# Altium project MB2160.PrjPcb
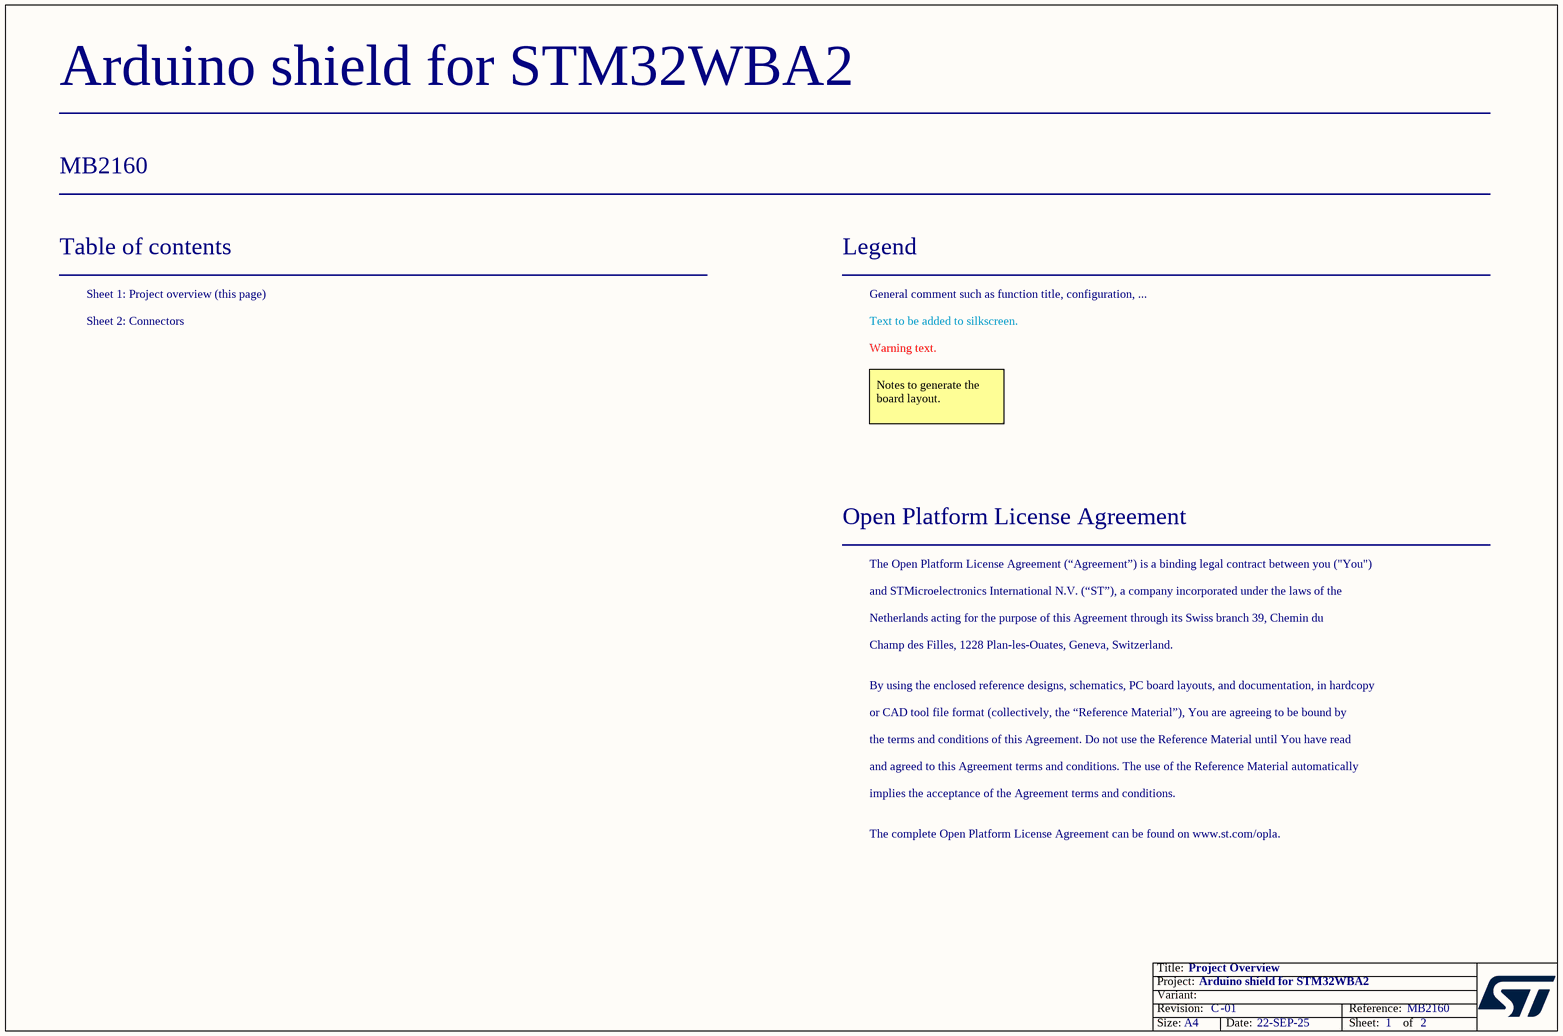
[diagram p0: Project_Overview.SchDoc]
Board_Reference: MB2160; Board_PCB_Revision: C; Board_Name: Arduino shield for STM32WBA2; Board_Document_Date: 22-SEP-25; Board_Assembly_Revision: 01
2 sheets, 28 parts. Net scope: global (net labels, ports and power ports of the same name join across sheets).
Board file: MB2160.PcbDoc
Sheets:
  Project_Overview.SchDoc
  Connectors.SchDoc

## Sheet Project_Overview.SchDoc: Project Overview
size A4; Date: Not used; ApprovedBy: Not used; CheckedBy: Not used; Author: Not used; CompanyName: STMicroelectronics; DrawnBy: Not used; Engineer: Not used; Organization: Not used; Address1: Not used; Address2: Not used; Address3: Not used; Address4: Not used; DocumentNumber: 1; Revision: Not used; SheetNumber: 1; SheetTotal: 2

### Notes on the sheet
- Table of contents
- Sheet 1: Project overview (this page)
- Legend
- General comment such as function title, configuration, ...
- Sheet 2: Connectors
- Text to be added to silkscreen.
- Warning text.
- Notes to generate the board layout.
- Open Platform License Agreement
- The Open Platform License Agreement (“Agreement”) is a binding legal contract between you ("You")
- and STMicroelectronics International N.V. (“ST”), a company incorporated under the laws of the
- Netherlands acting for the purpose of this Agreement through its Swiss branch 39, Chemin du
- Champ des Filles, 1228 Plan-les-Ouates, Geneva, Switzerland.
- By using the enclosed reference designs, schematics, PC board layouts, and documentation, in hardcopy
- or CAD tool file format (collectively, the “Reference Material”), You are agreeing to be bound by
- the terms and conditions of this Agreement. Do not use the Reference Material until You have read
- and agreed to this Agreement terms and conditions. The use of the Reference Material automatically
- implies the acceptance of the Agreement terms and conditions.
- The complete Open Platform License Agreement can be found on www.st.com/opla.

## Sheet Connectors.SchDoc: Arduino
size A4; Date: Not used; ApprovedBy: Not used; CheckedBy: Not used; Author: Not used; CompanyName: STMicroelectronics; DrawnBy: Not used; Engineer: Not used; Organization: Not used; Address1: Not used; Address2: Not used; Address3: Not used; Address4: Not used; DocumentNumber: 2; Revision: Not used; SheetNumber: 2; SheetTotal: 2
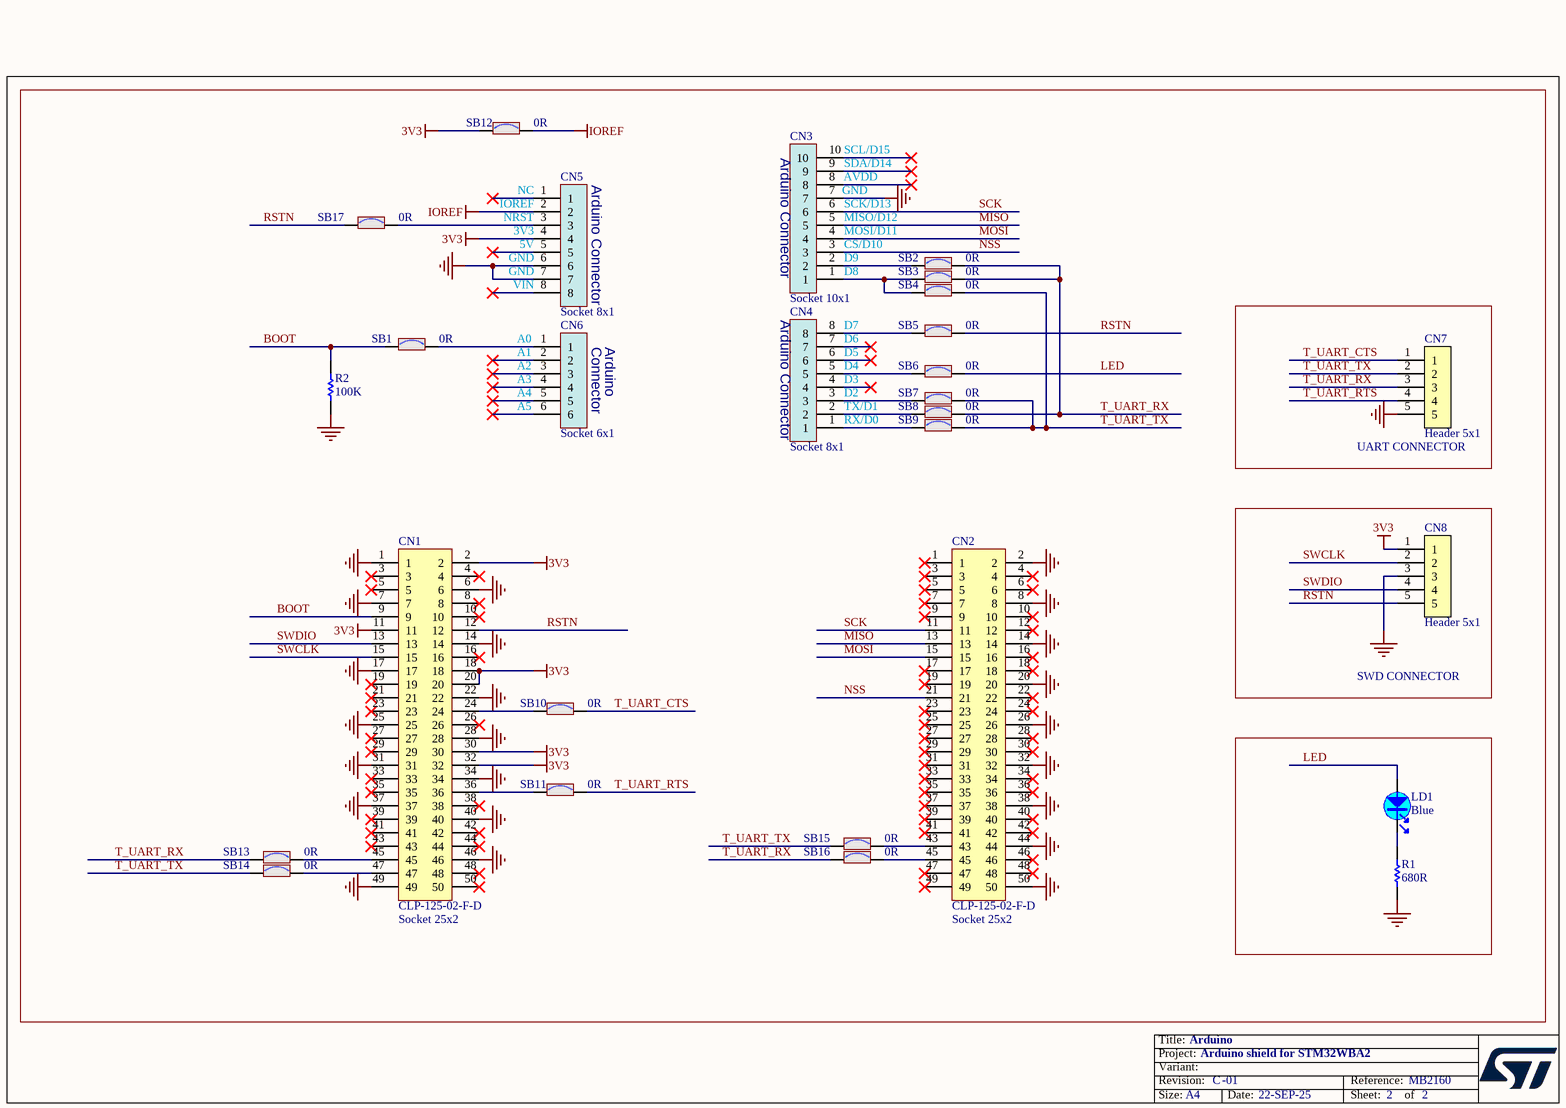
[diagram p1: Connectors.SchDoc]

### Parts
CN1  CLP-125-02-F-D  value Socket 25x2  [CON_SAMTEC_CLP-125-02-F-D]
CN2  CLP-125-02-F-D  value Socket 25x2  [CON_SAMTEC_CLP-125-02-F-D]
CN3  Socket 10x1  [CON_SAMTEC_SSQ-110-03-F-S]
CN4  Socket 8x1  [CON_SAMTEC_SSQ-108-03-F-S]
CN5  Socket 8x1  [CON_SAMTEC_SSQ-108-03-F-S]
CN6  Socket 6x1  [CON_SAMTEC_SSQ-106-03-F-S]
CN7  Header 5x1  [CON_SAMTEC_TSW-105-07-X-S]
CN8  Header 5x1  [CON_SAMTEC_TSW-105-07-X-S]
LD1  value Blue  [LED_0603_OSRAM_LB-Q39G-L2OO-35-1_BLUE_1A2K_H0P4]  (hidden comment: LED_blue)
R1  value 680R  [R0402]  (hidden comment: Resistor)
R2  value 100K  [R0402]  (hidden comment: Resistor)
SB1  value 0R  [SOLDER-BRIDGE_R0402-0R]  (hidden comment: SB_ON)
SB2  value 0R  [SOLDER-BRIDGE_R0402-0R]  (hidden comment: SB_ON)
SB3  value 0R  [SOLDER-BRIDGE_R0402-0R]  (hidden comment: SB_ON)
SB4  value 0R  [SOLDER-BRIDGE_R0402-0R]  (hidden comment: SB_ON)
SB5  value 0R  [SOLDER-BRIDGE_R0402-0R]  (hidden comment: SB_ON)
SB6  value 0R  [SOLDER-BRIDGE_R0402-0R]  (hidden comment: SB_ON)
SB7  value 0R  [SOLDER-BRIDGE_R0402-0R]  (hidden comment: SB_ON)
SB8  value 0R  [SOLDER-BRIDGE_R0402-0R]  (hidden comment: SB_ON)
SB9  value 0R  [SOLDER-BRIDGE_R0402-0R]  (hidden comment: SB_ON)
SB10  value 0R  [SOLDER-BRIDGE_R0402-0R]  (hidden comment: SB_ON)
SB11  value 0R  [SOLDER-BRIDGE_R0402-0R]  (hidden comment: SB_ON)
SB12  value 0R  [SOLDER-BRIDGE_R0402-0R]  (hidden comment: SB_ON)
SB13  value 0R  [SOLDER-BRIDGE_R0402-0R]  (hidden comment: SB_ON)
SB14  value 0R  [SOLDER-BRIDGE_R0402-0R]  (hidden comment: SB_ON)
SB15  value 0R  [SOLDER-BRIDGE_R0402-0R]  (hidden comment: SB_ON)
SB16  value 0R  [SOLDER-BRIDGE_R0402-0R]  (hidden comment: SB_ON)
SB17  value 0R  [SOLDER-BRIDGE_R0402-0R]  (hidden comment: SB_ON)

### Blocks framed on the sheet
UART CONNECTOR: CN7
SWD CONNECTOR: CN8

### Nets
3V3: CN1.2 CN1.11 CN1.18 CN1.20 CN1.30 CN1.32 CN5.4 CN8.1 SB12.1
GND: CN1.1 CN1.6 CN1.7 CN1.14 CN1.17 CN1.22 CN1.25 CN1.28 CN1.31 CN1.34 CN1.37 CN1.40 CN1.46 CN1.49 CN2.2 CN2.8 CN2.14 CN2.20 CN2.26 CN2.32 CN2.38 CN2.44 CN2.50 CN3.7 CN5.6 CN5.7 CN7.5 CN8.3 R1.1 R2.1
IOREF: CN5.2 SB12.2
BOOT: CN1.9 R2.2 SB1.1
LED: LD1.1 SB6.2
MISO: CN2.13 CN3.5
MOSI: CN2.15 CN3.4
NSS: CN2.21 CN3.3
RSTN: CN1.12 CN8.5 SB5.2 SB17.1
SCK: CN2.11 CN3.6
SWCLK: CN1.15 CN8.2
SWDIO: CN1.13 CN8.4
T_UART_CTS: CN7.1 SB10.2
T_UART_RTS: CN7.4 SB11.2
T_UART_RX: CN7.3 SB2.2 SB3.2 SB8.2 SB13.1 SB16.1
T_UART_TX: CN7.2 SB4.2 SB7.2 SB9.2 SB14.1 SB15.1
NetCN1_24: CN1.24 SB10.1
NetCN1_36: CN1.36 SB11.1
NetCN1_45: CN1.45 SB13.2
NetCN1_47: CN1.47 SB14.2
NetCN2_43: CN2.43 SB15.2
NetCN2_45: CN2.45 SB16.2
NetCN3_1: CN3.1 SB3.1 SB4.1
NetCN3_2: CN3.2 SB2.1
NetCN4_1: CN4.1 SB9.1
NetCN4_2: CN4.2 SB8.1
NetCN4_3: CN4.3 SB7.1
NetCN4_5: CN4.5 SB6.1
NetCN4_8: CN4.8 SB5.1
NetCN5_3: CN5.3 SB17.2
NetCN6_1: CN6.1 SB1.2
NetLD1_2: LD1.2 R1.2

Not connected (* = marked no-connect by the designer): CN1 3* 4* 5* 8* 10* 16* 19* 21* 23* 26* 27* 29* 33* 35* 38* 39* 41* 42* 43* 44* 48* 50*; CN2 1* 3* 4* 5* 6* 7* 9* 10* 12* 16* 17* 18* 19* 22* 23* 24* 25* 27* 28* 29* 30* 31* 33* 34* 35* 36* 37* 39* 40* 41* 42* 46* 47* 48* 49*; CN3 8* 9* 10*; CN4 4* 6* 7*; CN5 1* 5* 8*; CN6 2* 3* 4* 5* 6*

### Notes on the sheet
- (near CN5) Arduino Connector
- (near CN3) Arduino Connector
- (near CN3) SDA/D14
- (near CN3) SCL/D15
- (near CN3) AVDD
- (near CN5) NC
- (near CN5) IOREF
- (near CN5) NRST
- (near CN5) 3V3
- (near CN5) 5V
- (near CN3) CS/D10
- MOSI/D11
- (near CN3) MISO/D12
- (near CN3) SCK/D13
- (near CN3) GND
- (near CN5) GND
- (near CN5) VIN
- (near CN4) Arduino Connector
- (near CN3) D8
- (near CN3) D9
- (near CN6) A0
- (near CN6) A1
- (near CN6) A2
- (near CN6) A3
- (near CN6) Connector
- (near CN6) Arduino
- (near CN4) D7
- (near CN4) D6
- (near CN4) D5
- (near CN4) D4
- (near CN4) D3
- (near CN6) A4
- (near CN6) A5
- (near CN4) D2
- (near CN4) TX/D1
- (near CN4) RX/D0

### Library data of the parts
CN1 CN2 = MCD-02705: Socket, 25x2, 1.27mm, VR, SMD, T=2.29mm; Part_Type: Connector; Part_Preference: Recommended; Manufacturer: SAMTEC; Order_Code_RS: 180-3642; Component_Country_Of_Origin: USA; ShowFields: YES; ID: 4811
CN3 = MCD-02625: Socket, 10x1, 2.54mm, VR, TH, T=8.51mm/10mm; Part_Type: Connector; Part_Preference: Recommended; Manufacturer: SAMTEC; Manufacturer_Part_Number: SSQ-110-03-F-S; Order_Code_RS: 154-8308; Component_Country_Of_Origin: China, Costa Rica,  Malaysia, Vietnam, USA; ShowFields: YES; ID: 4731
CN4 CN5 = MCD-02624: Socket, 8x1, 2.54mm, VR, TH, T=8.51mm/10mm; Part_Type: Connector; Part_Preference: Recommended; Manufacturer: SAMTEC; Manufacturer_Part_Number: SSQ-108-03-F-S; Order_Code_RS: 180-0395; Component_Country_Of_Origin: China, Costa Rica,  Malaysia, Vietnam, USA; ShowFields: YES; ID: 4730
CN6 = MCD-02623: Socket, 6x1, 2.54mm, VR, TH, T=8.51mm/10mm; Part_Type: Connector; Part_Preference: Recommended; Manufacturer: SAMTEC; Manufacturer_Part_Number: SSQ-106-03-F-S; Order_Code_RS: 180-0379; Component_Country_Of_Origin: China, Costa Rica,  Malaysia, Vietnam, USA; ShowFields: YES; ID: 4729
CN7 CN8 = MCD-02060: Header, 5x1, 2.54mm, VR, TH, T=5.84mm/2.54mm; Part_Type: Connector; Part_Preference: Recommended; Manufacturer: SAMTEC; Manufacturer_Part_Number: TSW-105-07-G-S; Order_Code_RS: 161-2268; Component_Country_Of_Origin: China, Costa Rica, Malaysia, United States, Vietnam; ShowFields: YES; ID: 4160
LD1 = MCD-00585: LED, Blue, 2V85, 5mA, 0603; Part_Type: Display; Part_Preference: Recommended; Manufacturer: OSRAM OPTO SEMICONDUCTORS; Manufacturer_Part_Number: LB Q39G-L2OO-35-1; Full_Alternate_Internal_Part_Number: MCD-02398; Order_Code_RS: 9148643; Component_Country_Of_Origin: Unknown; ShowFields: YES; ID: 3159
R1 = MCD-00507: Resistor, 680R, 0402, +/-1%, 1/16W; Part_Preference: Recommended; Manufacturer: YAGEO; Manufacturer_Part_Number: RC0402FR-07680RL; Component_Country_Of_Origin: China; ShowFields: YES; ID: 3238
R2 = MCD-00059: Resistor, 100K, 0402, +/-1%, 1/16W; Part_Preference: Recommended; Manufacturer: YAGEO; Manufacturer_Part_Number: RC0402FR-07100KL; Partial_Alternate_Internal_Part_Number: MCD-03301; Order_Code_RS: 2421891; Component_Country_Of_Origin: China; ShowFields: YES; ID: 2533
SB1-SB17 = MCD-01618: Resistor, 0R, SB0402, 5%, 0.063W; Part_Preference: Recommended; Manufacturer: YAGEO; Manufacturer_Part_Number: RC0402JR-070RL; Order_Code_RS: 618-5804; Component_Country_Of_Origin: China; ShowFields: YES; ID: 3718

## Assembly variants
WB05N: not fitted R2 SB2 SB3 SB4 SB6 SB7 SB10 SB11 SB15 SB16 SB17
WBA2: not fitted R2 SB2 SB3 SB4 SB6 SB7 SB10 SB11 SB15 SB16 SB17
